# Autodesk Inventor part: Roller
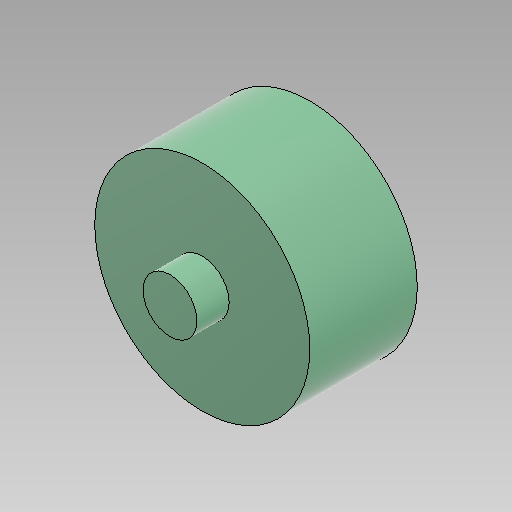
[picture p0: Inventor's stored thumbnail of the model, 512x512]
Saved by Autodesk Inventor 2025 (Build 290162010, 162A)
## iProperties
Created: 2024-10
Part Number: Roller
Material: Generic
Document SubType Name: Modeling
Designer: Dennis
Mass: 3.2594 g
Surface Area: 13.5088 cm^2
Volume: 3.2594 cm^3
Density: 1 g/cm^3
Appearance: Smooth - Dark Sea Green
Author: Dennis
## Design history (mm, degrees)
sketch "Sketch1"
  geometry: L1 (0, 8)-(0, -8); L2 (0, -8)-(2.5, -8); L3 (2.5, -8)-(2.5, -5); L4 (2.5, -5)-(10, -5); L5 (10, -5)-(10, 5); L6 (10, 5)-(2.5, 5); L7 (2.5, 5)-(2.5, 8); L8 (2.5, 8)-(0, 8); 2 further points
  constraints: 16 end point, 6 perpendicular, 2 point on line, 1 coincident, 1 collinear, 1 midpoint, 1 vertical
  dimensions: "d0" = 10 distance of L4.end L5.end; "d1" = 3 distance between parallel lines of L8 L6; "d2" = 5 diameter of L7 L1; "d3" = 20 diameter of L5 L1
revolve "Revolution1" sketch "Sketch1" stored, may be unused: angle "d4" = 90 deg
body "Solid1"
